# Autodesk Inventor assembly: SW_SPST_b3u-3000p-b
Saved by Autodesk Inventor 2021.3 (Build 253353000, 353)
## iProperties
Created: 2022-06
Part Number: SW_SPST_b3u-3000p-b
Document SubType Name: Assembly
Designer: Administrator
Title: SW_SPST_b3u-3000p-b
Author: Administrator
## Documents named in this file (2)
- c:\worker\convert-fusion-r03\tmp\job-1\203\output\files\98ba3c1f-9f0e-47fe-8659-38db50984f0d\SW_SPST_b3u-3000p-b.iam
- c:\worker\convert-fusion-r03\tmp\job-1\203\output\files\98ba3c1f-9f0e-47fe-8659-38db50984f0d\SOLID.ipt
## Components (1 placed, 1 different names)
1. SOLID:1
